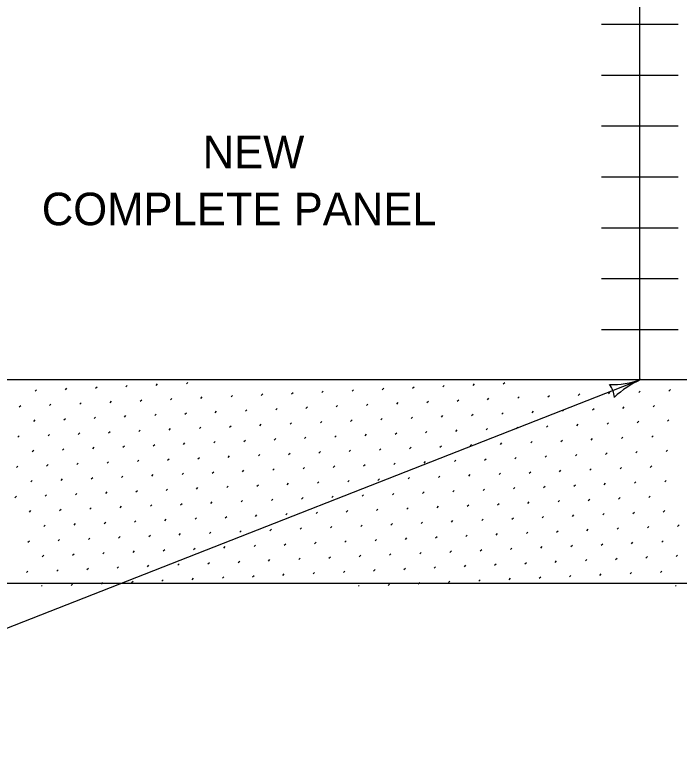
# Model space of a CAD drawing. Extents: x 49991.4 to 50021, y 49987.6 to 50011.4.
# Drawn here: x 50004.526 to 50006.156, y 49993.854 to 49995.687 of the extents above; entities that cross this region are included whole.
import ezdxf

# ---------------------------------------------------------------- set-up
doc = ezdxf.new("R2010")
doc.units = 0
for name, color, linetype in [('Level 1', 7, 'Continuous'), ('Level 10', 7, 'Continuous'), ('Level 2', 7, 'Continuous'), ('Level 3', 7, 'Continuous'), ('Level 4', 7, 'Continuous')]:
    doc.layers.add(name, color=color, linetype=linetype)

msp = doc.modelspace()

# ---------------------------------------------------------------- linework, layer by layer
at = {"layer": 'Level 1'}
for p, q in [((50006.0598, 49994.7903), (50006.0598, 49997.7903)), ((50007.9348, 49994.7903), (50002.3098, 49994.7903)), ((50015.1301, 49994.2903), (50001.3364, 49994.2903))]:
    msp.add_line(p, q, dxfattribs=at)
at = {"layer": 'Level 10'}
for p, q in [((50004.8725, 49994.777), (50004.8761, 49994.7805)), ((50004.9468, 49994.7805), (50004.9501, 49994.7838)), ((50005.6504, 49994.777), (50005.654, 49994.7806)), ((50005.7247, 49994.7806), (50005.728, 49994.7838)), ((50004.5755, 49994.7628), (50004.5791, 49994.7663)), ((50004.6498, 49994.7663), (50004.6533, 49994.7699)), ((50004.724, 49994.7699), (50004.7276, 49994.7734)), ((50004.7983, 49994.7734), (50004.8018, 49994.7769)), ((50005.2792, 49994.7593), (50005.2827, 49994.7628)), ((50005.3534, 49994.7629), (50005.357, 49994.7664)), ((50005.4277, 49994.7664), (50005.4312, 49994.7699)), ((50005.5019, 49994.7699), (50005.5055, 49994.7735)), ((50005.5762, 49994.7735), (50005.5797, 49994.777)), ((50006.0571, 49994.7594), (50006.0606, 49994.7629)), ((50006.1313, 49994.7629), (50006.1348, 49994.7665)), ((50004.9079, 49994.7416), (50004.9114, 49994.7451)), ((50004.9822, 49994.7451), (50004.9857, 49994.7487)), ((50005.0564, 49994.7487), (50005.0599, 49994.7522)), ((50005.1307, 49994.7522), (50005.1342, 49994.7558)), ((50005.2049, 49994.7558), (50005.2085, 49994.7593)), ((50005.6858, 49994.7417), (50005.6893, 49994.7452)), ((50005.76, 49994.7452), (50005.7636, 49994.7488)), ((50005.8343, 49994.7488), (50005.8378, 49994.7523)), ((50005.9086, 49994.7523), (50005.9121, 49994.7558)), ((50005.9828, 49994.7558), (50005.9863, 49994.7594)), ((50004.5366, 49994.7239), (50004.5402, 49994.7274)), ((50004.6109, 49994.7274), (50004.6144, 49994.731)), ((50004.6851, 49994.731), (50004.6887, 49994.7345)), ((50004.7594, 49994.7345), (50004.7629, 49994.7381)), ((50004.8337, 49994.7381), (50004.8372, 49994.7416)), ((50005.2403, 49994.7204), (50005.2438, 49994.724)), ((50005.3145, 49994.724), (50005.3181, 49994.7275)), ((50005.3888, 49994.7275), (50005.3923, 49994.731)), ((50005.463, 49994.731), (50005.4666, 49994.7346)), ((50005.5373, 49994.7346), (50005.5408, 49994.7381)), ((50005.6115, 49994.7381), (50005.6151, 49994.7417)), ((50006.0182, 49994.7205), (50006.0217, 49994.724)), ((50006.0924, 49994.724), (50006.0959, 49994.7276)), ((50004.869, 49994.7027), (50004.8725, 49994.7062)), ((50004.9433, 49994.7062), (50004.9468, 49994.7098)), ((50005.0175, 49994.7098), (50005.021, 49994.7133)), ((50005.0918, 49994.7133), (50005.0953, 49994.7169)), ((50005.166, 49994.7169), (50005.1696, 49994.7204)), ((50005.6469, 49994.7028), (50005.6504, 49994.7063)), ((50005.7211, 49994.7063), (50005.7247, 49994.7099)), ((50005.7954, 49994.7099), (50005.7989, 49994.7134)), ((50005.8697, 49994.7134), (50005.8732, 49994.7169)), ((50005.9439, 49994.7169), (50005.9474, 49994.7205)), ((50004.572, 49994.6885), (50004.5755, 49994.6921)), ((50004.6462, 49994.6921), (50004.6498, 49994.6956)), ((50004.7205, 49994.6956), (50004.724, 49994.6992)), ((50004.7948, 49994.6992), (50004.7983, 49994.7027)), ((50005.2756, 49994.6851), (50005.2792, 49994.6886)), ((50005.3499, 49994.6886), (50005.3534, 49994.6921)), ((50005.4241, 49994.6921), (50005.4277, 49994.6957)), ((50005.4984, 49994.6957), (50005.5019, 49994.6992)), ((50005.5726, 49994.6992), (50005.5762, 49994.7028)), ((50006.0535, 49994.6851), (50006.0571, 49994.6887)), ((50006.1278, 49994.6887), (50006.1313, 49994.6922)), ((50004.9044, 49994.6673), (50004.9079, 49994.6709)), ((50004.9786, 49994.6709), (50004.9822, 49994.6744)), ((50005.0529, 49994.6744), (50005.0564, 49994.678)), ((50005.1271, 49994.678), (50005.1307, 49994.6815)), ((50005.2014, 49994.6815), (50005.2049, 49994.6851)), ((50005.6822, 49994.6674), (50005.6858, 49994.671)), ((50005.7565, 49994.671), (50005.76, 49994.6745)), ((50005.8308, 49994.6745), (50005.8343, 49994.678)), ((50005.905, 49994.678), (50005.9085, 49994.6816)), ((50005.9793, 49994.6816), (50005.9828, 49994.6851)), ((50004.5331, 49994.6496), (50004.5366, 49994.6532)), ((50004.6073, 49994.6532), (50004.6109, 49994.6567)), ((50004.6816, 49994.6567), (50004.6851, 49994.6603)), ((50004.7559, 49994.6603), (50004.7594, 49994.6638)), ((50004.8301, 49994.6638), (50004.8336, 49994.6673)), ((50005.311, 49994.6497), (50005.3145, 49994.6532)), ((50005.3852, 49994.6532), (50005.3888, 49994.6568)), ((50005.4595, 49994.6568), (50005.463, 49994.6603)), ((50005.5337, 49994.6603), (50005.5373, 49994.6639)), ((50005.608, 49994.6639), (50005.6115, 49994.6674)), ((50006.0889, 49994.6498), (50006.0924, 49994.6533)), ((50004.9397, 49994.632), (50004.9433, 49994.6355)), ((50005.014, 49994.6355), (50005.0175, 49994.6391)), ((50005.0882, 49994.6391), (50005.0918, 49994.6426)), ((50005.1625, 49994.6426), (50005.166, 49994.6462)), ((50005.2367, 49994.6462), (50005.2403, 49994.6497)), ((50005.7176, 49994.6321), (50005.7211, 49994.6356)), ((50005.7919, 49994.6356), (50005.7954, 49994.6391)), ((50005.8661, 49994.6391), (50005.8696, 49994.6427)), ((50005.9404, 49994.6427), (50005.9439, 49994.6462)), ((50006.0146, 49994.6462), (50006.0182, 49994.6498)), ((50004.5685, 49994.6143), (50004.572, 49994.6178)), ((50004.6427, 49994.6178), (50004.6462, 49994.6214)), ((50004.717, 49994.6214), (50004.7205, 49994.6249)), ((50004.7912, 49994.6249), (50004.7947, 49994.6284)), ((50004.8655, 49994.6284), (50004.869, 49994.632)), ((50005.2721, 49994.6108), (50005.2756, 49994.6143)), ((50005.3463, 49994.6144), (50005.3499, 49994.6179)), ((50005.4206, 49994.6179), (50005.4241, 49994.6214)), ((50005.4948, 49994.6214), (50005.4984, 49994.625)), ((50005.5691, 49994.625), (50005.5726, 49994.6285)), ((50005.6434, 49994.6285), (50005.6469, 49994.6321)), ((50006.05, 49994.6109), (50006.0535, 49994.6144)), ((50006.1242, 49994.6144), (50006.1278, 49994.618)), ((50004.9008, 49994.5931), (50004.9044, 49994.5966)), ((50004.9751, 49994.5966), (50004.9786, 49994.6002)), ((50005.0493, 49994.6002), (50005.0529, 49994.6037)), ((50005.1236, 49994.6037), (50005.1271, 49994.6073)), ((50005.1978, 49994.6073), (50005.2014, 49994.6108)), ((50005.6787, 49994.5932), (50005.6822, 49994.5967)), ((50005.753, 49994.5967), (50005.7565, 49994.6002)), ((50005.8272, 49994.6003), (50005.8307, 49994.6038)), ((50005.9015, 49994.6038), (50005.905, 49994.6073)), ((50005.9757, 49994.6073), (50005.9793, 49994.6109)), ((50004.5296, 49994.5754), (50004.5331, 49994.5789)), ((50004.6038, 49994.5789), (50004.6073, 49994.5825)), ((50004.6781, 49994.5825), (50004.6816, 49994.586)), ((50004.7523, 49994.586), (50004.7558, 49994.5895)), ((50004.8266, 49994.5896), (50004.8301, 49994.5931)), ((50005.3074, 49994.5755), (50005.311, 49994.579)), ((50005.3817, 49994.579), (50005.3852, 49994.5825)), ((50005.4559, 49994.5825), (50005.4595, 49994.5861)), ((50005.5302, 49994.5861), (50005.5337, 49994.5896)), ((50005.6045, 49994.5896), (50005.608, 49994.5932)), ((50006.0853, 49994.5755), (50006.0889, 49994.5791)), ((50004.9362, 49994.5577), (50004.9397, 49994.5613)), ((50005.0104, 49994.5613), (50005.014, 49994.5648)), ((50005.0847, 49994.5648), (50005.0882, 49994.5684)), ((50005.1589, 49994.5684), (50005.1625, 49994.5719)), ((50005.2332, 49994.5719), (50005.2367, 49994.5754)), ((50005.7141, 49994.5578), (50005.7176, 49994.5613)), ((50005.7883, 49994.5614), (50005.7919, 49994.5649)), ((50005.8626, 49994.5649), (50005.8661, 49994.5684)), ((50005.9368, 49994.5684), (50005.9404, 49994.572)), ((50006.0111, 49994.572), (50006.0146, 49994.5755)), ((50004.5649, 49994.54), (50004.5684, 49994.5436)), ((50004.6392, 49994.5436), (50004.6427, 49994.5471)), ((50004.7134, 49994.5471), (50004.7169, 49994.5506)), ((50004.7877, 49994.5507), (50004.7912, 49994.5542)), ((50004.8619, 49994.5542), (50004.8655, 49994.5577)), ((50005.3428, 49994.5401), (50005.3463, 49994.5436)), ((50005.417, 49994.5436), (50005.4206, 49994.5472)), ((50005.4913, 49994.5472), (50005.4948, 49994.5507)), ((50005.5656, 49994.5507), (50005.5691, 49994.5543)), ((50005.6398, 49994.5543), (50005.6433, 49994.5578)), ((50006.1207, 49994.5402), (50006.1242, 49994.5437)), ((50004.8973, 49994.5188), (50004.9008, 49994.5224)), ((50004.9715, 49994.5224), (50004.9751, 49994.5259)), ((50005.0458, 49994.5259), (50005.0493, 49994.5295)), ((50005.12, 49994.5295), (50005.1236, 49994.533)), ((50005.1943, 49994.533), (50005.1978, 49994.5365)), ((50005.2685, 49994.5366), (50005.2721, 49994.5401)), ((50005.6752, 49994.5189), (50005.6787, 49994.5224)), ((50005.7494, 49994.5225), (50005.753, 49994.526)), ((50005.8237, 49994.526), (50005.8272, 49994.5295)), ((50005.8979, 49994.5295), (50005.9015, 49994.5331)), ((50005.9722, 49994.5331), (50005.9757, 49994.5366)), ((50006.0464, 49994.5366), (50006.05, 49994.5402)), ((50004.526, 49994.5011), (50004.5295, 49994.5047)), ((50004.6003, 49994.5047), (50004.6038, 49994.5082)), ((50004.6745, 49994.5082), (50004.6781, 49994.5117)), ((50004.7488, 49994.5118), (50004.7523, 49994.5153)), ((50004.823, 49994.5153), (50004.8266, 49994.5188)), ((50005.3039, 49994.5012), (50005.3074, 49994.5047)), ((50005.3782, 49994.5047), (50005.3817, 49994.5083)), ((50005.4524, 49994.5083), (50005.4559, 49994.5118)), ((50005.5267, 49994.5118), (50005.5302, 49994.5154)), ((50005.6009, 49994.5154), (50005.6044, 49994.5189)), ((50006.0818, 49994.5013), (50006.0853, 49994.5048)), ((50004.9326, 49994.4835), (50004.9362, 49994.487)), ((50005.0069, 49994.487), (50005.0104, 49994.4906)), ((50005.0811, 49994.4906), (50005.0847, 49994.4941)), ((50005.1554, 49994.4941), (50005.1589, 49994.4976)), ((50005.2296, 49994.4977), (50005.2332, 49994.5012)), ((50005.7105, 49994.4836), (50005.7141, 49994.4871)), ((50005.7848, 49994.4871), (50005.7883, 49994.4906)), ((50005.859, 49994.4906), (50005.8626, 49994.4942)), ((50005.9333, 49994.4942), (50005.9368, 49994.4977)), ((50006.0075, 49994.4977), (50006.0111, 49994.5013)), ((50004.5614, 49994.4658), (50004.5649, 49994.4693)), ((50004.6356, 49994.4693), (50004.6392, 49994.4729)), ((50004.7099, 49994.4729), (50004.7134, 49994.4764)), ((50004.7841, 49994.4764), (50004.7877, 49994.4799)), ((50004.8584, 49994.4799), (50004.8619, 49994.4835)), ((50005.3393, 49994.4658), (50005.3428, 49994.4694)), ((50005.4135, 49994.4694), (50005.417, 49994.4729)), ((50005.4878, 49994.4729), (50005.4913, 49994.4765)), ((50005.562, 49994.4765), (50005.5655, 49994.48)), ((50005.6363, 49994.48), (50005.6398, 49994.4835)), ((50006.1171, 49994.4659), (50006.1207, 49994.4694)), ((50004.968, 49994.4481), (50004.9715, 49994.4517)), ((50005.0422, 49994.4517), (50005.0458, 49994.4552)), ((50005.1165, 49994.4552), (50005.12, 49994.4588)), ((50005.1907, 49994.4588), (50005.1943, 49994.4623)), ((50005.265, 49994.4623), (50005.2685, 49994.4658)), ((50005.7459, 49994.4482), (50005.7494, 49994.4517)), ((50005.8201, 49994.4517), (50005.8237, 49994.4553)), ((50005.8944, 49994.4553), (50005.8979, 49994.4588)), ((50005.9686, 49994.4588), (50005.9722, 49994.4624)), ((50006.0429, 49994.4624), (50006.0464, 49994.4659)), ((50004.5967, 49994.4304), (50004.6003, 49994.434)), ((50004.671, 49994.434), (50004.6745, 49994.4375)), ((50004.7452, 49994.4375), (50004.7488, 49994.441)), ((50004.8195, 49994.441), (50004.823, 49994.4446)), ((50004.8937, 49994.4446), (50004.8973, 49994.4481)), ((50005.3746, 49994.4305), (50005.3781, 49994.434)), ((50005.4489, 49994.434), (50005.4524, 49994.4376)), ((50005.5231, 49994.4376), (50005.5267, 49994.4411)), ((50005.5974, 49994.4411), (50005.6009, 49994.4447)), ((50005.6716, 49994.4447), (50005.6752, 49994.4482)), ((50006.1525, 49994.4306), (50006.156, 49994.4341)), ((50004.9291, 49994.4092), (50004.9326, 49994.4128)), ((50005.0033, 49994.4128), (50005.0069, 49994.4163)), ((50005.0776, 49994.4163), (50005.0811, 49994.4199)), ((50005.1518, 49994.4199), (50005.1554, 49994.4234)), ((50005.2261, 49994.4234), (50005.2296, 49994.4269)), ((50005.3004, 49994.4269), (50005.3039, 49994.4305)), ((50005.707, 49994.4093), (50005.7105, 49994.4128)), ((50005.7812, 49994.4128), (50005.7848, 49994.4164)), ((50005.8555, 49994.4164), (50005.859, 49994.4199)), ((50005.9297, 49994.4199), (50005.9333, 49994.4235)), ((50006.004, 49994.4235), (50006.0075, 49994.427)), ((50006.0782, 49994.427), (50006.0818, 49994.4306)), ((50004.5578, 49994.3915), (50004.5614, 49994.3951)), ((50004.6321, 49994.3951), (50004.6356, 49994.3986)), ((50004.7063, 49994.3986), (50004.7099, 49994.4021)), ((50004.7806, 49994.4021), (50004.7841, 49994.4057)), ((50004.8548, 49994.4057), (50004.8584, 49994.4092)), ((50005.3357, 49994.3916), (50005.3392, 49994.3951)), ((50005.41, 49994.3951), (50005.4135, 49994.3987)), ((50005.4842, 49994.3987), (50005.4878, 49994.4022)), ((50005.5585, 49994.4022), (50005.562, 49994.4058)), ((50005.6327, 49994.4058), (50005.6363, 49994.4093)), ((50006.1136, 49994.3917), (50006.1171, 49994.3952)), ((50004.9644, 49994.3739), (50004.968, 49994.3774)), ((50005.0387, 49994.3774), (50005.0422, 49994.381)), ((50005.113, 49994.381), (50005.1165, 49994.3845)), ((50005.1872, 49994.3845), (50005.1907, 49994.388)), ((50005.2615, 49994.388), (50005.265, 49994.3916)), ((50005.7423, 49994.3739), (50005.7459, 49994.3775)), ((50005.8166, 49994.3775), (50005.8201, 49994.381)), ((50005.8908, 49994.381), (50005.8944, 49994.3846)), ((50005.9651, 49994.3846), (50005.9686, 49994.3881)), ((50006.0393, 49994.3881), (50006.0429, 49994.3917)), ((50004.5932, 49994.3562), (50004.5967, 49994.3597)), ((50004.6674, 49994.3597), (50004.671, 49994.3632)), ((50004.7417, 49994.3632), (50004.7452, 49994.3668)), ((50004.8159, 49994.3668), (50004.8195, 49994.3703)), ((50004.8902, 49994.3703), (50004.8937, 49994.3739)), ((50005.3711, 49994.3562), (50005.3746, 49994.3598)), ((50005.4453, 49994.3598), (50005.4489, 49994.3633)), ((50005.5196, 49994.3633), (50005.5231, 49994.3669)), ((50005.5938, 49994.3669), (50005.5974, 49994.3704)), ((50005.6681, 49994.3704), (50005.6716, 49994.3739)), ((50006.149, 49994.3563), (50006.1525, 49994.3598)), ((50004.9998, 49994.3385), (50005.0033, 49994.3421)), ((50005.0741, 49994.3421), (50005.0776, 49994.3456)), ((50005.1483, 49994.3456), (50005.1518, 49994.3491)), ((50005.2226, 49994.3491), (50005.2261, 49994.3527)), ((50005.2968, 49994.3527), (50005.3003, 49994.3562)), ((50005.7777, 49994.3386), (50005.7812, 49994.3421)), ((50005.8519, 49994.3421), (50005.8555, 49994.3457)), ((50005.9262, 49994.3457), (50005.9297, 49994.3492)), ((50006.0004, 49994.3492), (50006.004, 49994.3528)), ((50006.0747, 49994.3528), (50006.0782, 49994.3563)), ((50004.5543, 49994.3173), (50004.5578, 49994.3208)), ((50004.6285, 49994.3208), (50004.6321, 49994.3243)), ((50004.7028, 49994.3244), (50004.7063, 49994.3279)), ((50004.777, 49994.3279), (50004.7806, 49994.3314)), ((50004.8513, 49994.3314), (50004.8548, 49994.335)), ((50004.9255, 49994.335), (50004.9291, 49994.3385)), ((50005.3322, 49994.3173), (50005.3357, 49994.3209)), ((50005.4064, 49994.3209), (50005.41, 49994.3244)), ((50005.4807, 49994.3244), (50005.4842, 49994.328)), ((50005.5549, 49994.328), (50005.5585, 49994.3315)), ((50005.6292, 49994.3315), (50005.6327, 49994.335)), ((50005.7034, 49994.3351), (50005.707, 49994.3386)), ((50006.1101, 49994.3174), (50006.1136, 49994.3209)), ((50004.9609, 49994.2996), (50004.9644, 49994.3032)), ((50005.0352, 49994.3032), (50005.0387, 49994.3067)), ((50005.1094, 49994.3067), (50005.1129, 49994.3102)), ((50005.1837, 49994.3103), (50005.1872, 49994.3138)), ((50005.2579, 49994.3138), (50005.2615, 49994.3173)), ((50005.7388, 49994.2997), (50005.7423, 49994.3032)), ((50005.813, 49994.3032), (50005.8166, 49994.3068)), ((50005.8873, 49994.3068), (50005.8908, 49994.3103)), ((50005.9615, 49994.3103), (50005.9651, 49994.3139)), ((50006.0358, 49994.3139), (50006.0393, 49994.3174)), ((50004.5916, 49994.2838), (50004.5932, 49994.2854)), ((50004.6639, 49994.2855), (50004.6674, 49994.289)), ((50004.7381, 49994.289), (50004.7417, 49994.2925)), ((50004.8124, 49994.2925), (50004.8159, 49994.2961)), ((50004.8866, 49994.2961), (50004.8902, 49994.2996)), ((50005.3694, 49994.2838), (50005.3711, 49994.2855)), ((50005.4418, 49994.2855), (50005.4453, 49994.2891)), ((50005.516, 49994.2891), (50005.5196, 49994.2926)), ((50005.5903, 49994.2926), (50005.5938, 49994.2961)), ((50005.6645, 49994.2962), (50005.6681, 49994.2997)), ((50006.1472, 49994.2838), (50006.1489, 49994.2856))]:
    msp.add_line(p, q, dxfattribs=at)
at = {"layer": 'Level 3'}
msp.add_line((50003.6725, 49993.8542), (50006.0598, 49994.7903), dxfattribs=at)
for centre, radius, start, end in [((50005.9894, 49995.0012), 0.2223, 268.8675, 289.051), ((50005.9426, 49994.7442), 0.0548, 3.5503, 39.2727), ((50006.1576, 49994.5786), 0.233, 114.2388, 133.4887)]:
    msp.add_arc(centre, radius, start, end, dxfattribs=at)
at = {"layer": 'Level 4'}
for p, q in [((50005.966, 49995.6642), (50006.1535, 49995.6642)), ((50005.966, 49995.5392), (50006.1535, 49995.5392)), ((50005.966, 49995.4142), (50006.1535, 49995.4142)), ((50005.966, 49995.2892), (50006.1535, 49995.2892)), ((50005.966, 49995.1642), (50006.1535, 49995.1642)), ((50005.966, 49995.0392), (50006.1535, 49995.0392)), ((50005.966, 49994.9142), (50006.1535, 49994.9142))]:
    msp.add_line(p, q, dxfattribs=at)

# ---------------------------------------------------------------- texts
at = {"layer": 'Level 2'}
for s, p in [('NEW', (50004.9867, 49995.3103)), ('COMPLETE PANEL', (50004.5919, 49995.1703))]:
    msp.add_text(s, height=0.08, dxfattribs=at).set_placement(p)

doc.saveas('drawing.dxf')
